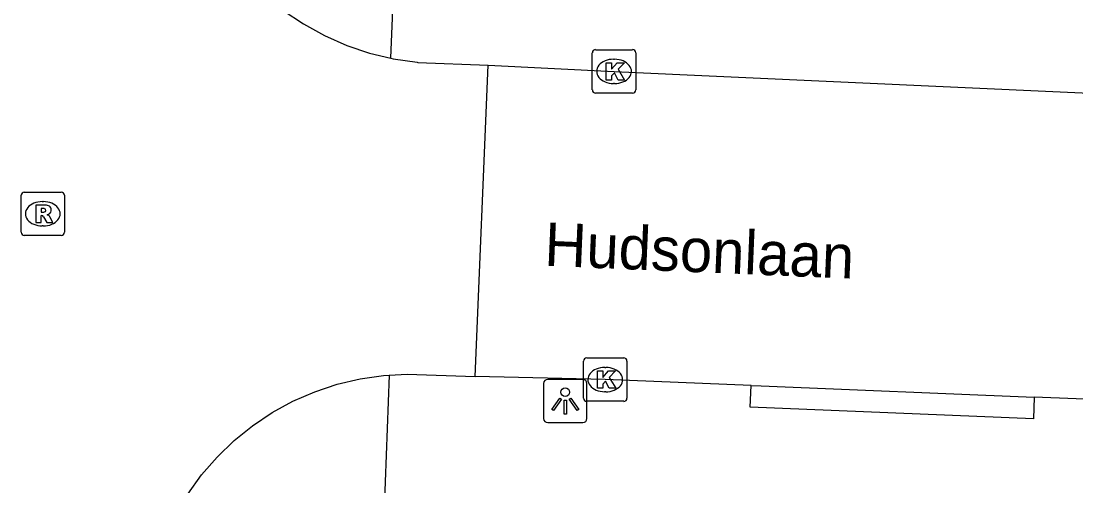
# Model space of a CAD drawing. Extents: x 161253 to 161848, y 384872 to 385383.
# Drawn here: x 161651.15 to 161675.46, y 384938.23 to 384948.95 of the extents above; entities that cross this region are included whole.
import ezdxf

# ---------------------------------------------------------------- set-up
doc = ezdxf.new("R2010")
doc.units = 0
for name, color, linetype in [('IMGEO_Kolk', 7, 'Continuous'), ('IMGEO_Lichtpunt', 7, 'Continuous'), ('IMGEO_Openbare_ruimte_label', 7, 'Continuous'), ('IMGEO_Rijbaan_lokaal_open', 7, 'Continuous'), ('IMGEO_Rioolput', 7, 'Continuous'), ('IMGEO_Voetpad_open', 7, 'Continuous')]:
    doc.layers.add(name, color=color, linetype=linetype)

msp = doc.modelspace()

# ---------------------------------------------------------------- linework, layer by layer
at = {"layer": 'IMGEO_Kolk'}
for p, q in [((161664.312, 384947.367), (161664.312, 384948.219)), ((161664.387, 384948.293), (161665.239, 384948.293)), ((161665.313, 384948.219), (161665.313, 384947.367)), ((161664.8, 384948.073), (161664.825, 384948.073)), ((161664.823, 384947.513), (161664.798, 384947.513)), ((161665.239, 384947.293), (161664.387, 384947.293)), ((161664.184, 384941.184), (161665.036, 384941.184)), ((161664.109, 384940.258), (161664.109, 384941.11)), ((161664.597, 384940.964), (161664.622, 384940.964)), ((161665.11, 384941.11), (161665.11, 384940.258)), ((161664.62, 384940.404), (161664.595, 384940.404)), ((161665.036, 384940.184), (161664.184, 384940.184))]:
    msp.add_line(p, q, dxfattribs=at)
for points in [[(161664.312, 384947.367), (161664.312, 384948.219)], [(161664.387, 384948.293), (161665.239, 384948.293)], [(161665.313, 384948.219), (161665.313, 384947.367)], [(161664.633, 384947.993), (161664.756, 384947.993), (161664.756, 384947.842), (161664.886, 384947.993), (161665.05, 384947.993), (161664.904, 384947.842), (161665.057, 384947.593), (161664.905, 384947.593), (161664.82, 384947.757), (161664.756, 384947.69), (161664.756, 384947.593), (161664.633, 384947.593), (161664.633, 384947.993)], [(161665.239, 384947.293), (161664.387, 384947.293)], [(161664.184, 384941.184), (161665.036, 384941.184)], [(161664.109, 384940.258), (161664.109, 384941.11)], [(161665.11, 384941.11), (161665.11, 384940.258)], [(161664.43, 384940.884), (161664.553, 384940.884), (161664.553, 384940.733), (161664.683, 384940.884), (161664.847, 384940.884), (161664.701, 384940.733), (161664.854, 384940.484), (161664.702, 384940.484), (161664.617, 384940.648), (161664.553, 384940.581), (161664.553, 384940.484), (161664.43, 384940.484), (161664.43, 384940.884)], [(161665.036, 384940.184), (161664.184, 384940.184)]]:
    msp.add_lwpolyline(points, dxfattribs=at)
for centre, start, end in [((161664.389, 384948.217), 91.552, 178.448), ((161664.389, 384948.217), 91.552, 178.448), ((161665.237, 384948.217), 1.552, 88.448), ((161665.237, 384948.217), 1.552, 88.448), ((161664.389, 384947.369), 181.552, 268.448), ((161664.389, 384947.369), 181.552, 268.448), ((161665.237, 384947.369), 271.552, 358.448), ((161665.237, 384947.369), 271.552, 358.448), ((161664.186, 384941.108), 91.552, 178.448), ((161664.186, 384941.108), 91.552, 178.448), ((161665.034, 384941.108), 1.552, 88.448), ((161665.034, 384941.108), 1.552, 88.448), ((161664.186, 384940.26), 181.552, 268.448), ((161664.186, 384940.26), 181.552, 268.448), ((161665.034, 384940.26), 271.552, 358.448), ((161665.034, 384940.26), 271.552, 358.448)]:
    msp.add_arc(centre, 0.0765, start, end, dxfattribs=at)
for centre, major_axis, ratio, start_param, end_param in [((161664.799, 384947.793), (-0.387, 0.002), 0.722429, 4.712389, 7.853982), ((161664.824, 384947.793), (-0.39, 0.002), 0.717154, 1.570796, 4.712389), ((161664.596, 384940.684), (-0.387, 0.002), 0.722429, 4.712389, 7.853982), ((161664.621, 384940.684), (-0.39, 0.002), 0.717154, 1.570796, 4.712389)]:
    msp.add_ellipse(centre, major_axis=major_axis, ratio=ratio, start_param=start_param, end_param=end_param, dxfattribs=at)
at = {"layer": 'IMGEO_Lichtpunt'}
for p, q in [((161664.092, 384940.691), (161663.284, 384940.691)), ((161664.092, 384940.691), (161663.284, 384940.691)), ((161663.19, 384940.596), (161663.19, 384939.789)), ((161663.19, 384940.596), (161663.19, 384939.789)), ((161664.186, 384939.789), (161664.186, 384940.596)), ((161664.186, 384939.789), (161664.186, 384940.596)), ((161663.284, 384939.695), (161664.092, 384939.695)), ((161663.284, 384939.695), (161664.092, 384939.695))]:
    msp.add_line(p, q, dxfattribs=at)
for points in [[(161663.564, 384940.26), (161663.603, 384940.232), (161663.415, 384939.97), (161663.377, 384939.997), (161663.564, 384940.26)], [(161663.666, 384940.212), (161663.713, 384940.212), (161663.713, 384939.89), (161663.666, 384939.89), (161663.666, 384940.212)], [(161663.776, 384940.232), (161663.814, 384940.259), (161664.001, 384939.997), (161663.962, 384939.969), (161663.776, 384940.232)]]:
    msp.add_lwpolyline(points, dxfattribs=at)
msp.add_circle((161663.689, 384940.394), 0.0994, dxfattribs=at)
for centre, start, end in [((161663.284, 384940.596), 90, 180), ((161663.284, 384940.596), 90, 180), ((161664.092, 384940.596), 0, 90), ((161664.092, 384940.596), 0, 90), ((161663.284, 384939.789), 180, 270), ((161663.284, 384939.789), 180, 270), ((161664.092, 384939.789), 270, 0), ((161664.092, 384939.789), 270, 360)]:
    msp.add_arc(centre, 0.0946, start, end, dxfattribs=at)
at = {"layer": 'IMGEO_Rijbaan_lokaal_open'}
for points in [[(161654.717, 384956.106), (161654.675, 384954.531), (161654.672, 384953.973), (161654.718, 384953.417), (161654.813, 384952.867), (161654.958, 384952.328), (161655.15, 384951.804), (161655.388, 384951.299), (161655.67, 384950.818), (161655.994, 384950.364), (161656.357, 384949.94), (161656.757, 384949.551), (161657.19, 384949.199), (161657.652, 384948.887), (161658.141, 384948.617), (161658.651, 384948.393), (161659.18, 384948.214), (161659.665, 384948.098)], [(161661.913, 384947.934), (161664.813, 384947.793), (161680.659, 384947.069), (161681.376, 384947.063), (161682.091, 384947.121), (161682.798, 384947.242), (161683.491, 384947.426), (161684.165, 384947.672), (161684.814, 384947.976), (161685.433, 384948.338), (161686.018, 384948.753), (161686.563, 384949.219), (161687.065, 384949.731), (161687.518, 384950.287), (161687.921, 384950.88), (161688.268, 384951.508), (161688.558, 384952.163), (161688.789, 384952.843), (161688.958, 384953.539), (161689.064, 384954.249), (161689.098, 384954.71), (161689.115, 384955.181)], [(161659.665, 384948.098), (161659.723, 384948.084), (161660.275, 384948.003), (161660.291, 384948.001), (161661.913, 384947.934)], [(161661.612, 384940.759), (161661.913, 384947.934)], [(161653.829, 384931.155), (161654.012, 384935.141), (161654.049, 384935.508), (161654.145, 384936.045), (161654.288, 384936.571), (161654.478, 384937.083), (161654.712, 384937.575), (161654.99, 384938.045), (161655.308, 384938.488), (161655.665, 384938.9), (161656.057, 384939.279), (161656.481, 384939.622), (161656.935, 384939.925), (161657.413, 384940.187), (161657.913, 384940.404), (161658.431, 384940.577), (161658.962, 384940.702), (161659.502, 384940.779), (161659.633, 384940.786)], [(161659.633, 384940.786), (161660.046, 384940.808), (161661.612, 384940.759)], [(161667.973, 384940.551), (161664.61, 384940.684), (161661.612, 384940.759)], [(161667.973, 384940.551), (161668.201, 384940.542), (161674.499, 384940.279)], [(161695.406, 384939.447), (161674.499, 384940.279)]]:
    msp.add_lwpolyline(points, dxfattribs=at)
at = {"layer": 'IMGEO_Rioolput'}
for p, q in [((161651.146, 384944.083), (161651.146, 384944.935)), ((161651.221, 384945.009), (161652.073, 384945.009)), ((161652.147, 384944.935), (161652.147, 384944.083)), ((161651.634, 384944.789), (161651.659, 384944.789)), ((161651.657, 384944.229), (161651.632, 384944.229)), ((161652.073, 384944.009), (161651.221, 384944.009))]:
    msp.add_line(p, q, dxfattribs=at)
for points in [[(161651.146, 384944.083), (161651.146, 384944.935)], [(161651.221, 384945.009), (161652.073, 384945.009)], [(161652.147, 384944.935), (161652.147, 384944.083)], [(161651.735, 384944.707), (161651.483, 384944.709), (161651.483, 384944.309)], [(161651.661, 384944.628), (161651.607, 384944.628), (161651.607, 384944.547)], [(161651.483, 384944.309), (161651.607, 384944.309), (161651.607, 384944.471), (161651.618, 384944.471)], [(161651.607, 384944.547), (161651.659, 384944.547)], [(161651.665, 384944.442), (161651.736, 384944.309), (161651.876, 384944.309), (161651.811, 384944.435)], [(161652.073, 384944.009), (161651.221, 384944.009)]]:
    msp.add_lwpolyline(points, dxfattribs=at)
for centre, radius, start, end in [((161651.223, 384944.933), 0.0765, 91.552, 178.448), ((161651.223, 384944.933), 0.0765, 91.552, 178.448), ((161652.071, 384944.933), 0.0765, 1.552, 88.448), ((161652.071, 384944.933), 0.0765, 1.552, 88.448), ((161651.667, 384944.532), 0.0964, 77.0061, 93.1865), ((161651.681, 384944.589), 0.0378, 276.6634, 79.6772), ((161651.734, 384944.597), 0.109, 350.3612, 89.416), ((161651.732, 384944.597), 0.112, 277.5842, 350.9817), ((161651.617, 384944.418), 0.0533, 26.0293, 88.6989), ((161651.643, 384944.736), 0.19, 274.7715, 282.9687), ((161651.716, 384944.382), 0.108, 29.5134, 73.7905), ((161651.223, 384944.085), 0.0765, 181.552, 268.448), ((161651.223, 384944.085), 0.0765, 181.552, 268.448), ((161652.071, 384944.085), 0.0765, 271.552, 358.448), ((161652.071, 384944.085), 0.0765, 271.552, 358.448)]:
    msp.add_arc(centre, radius, start, end, dxfattribs=at)
for centre, major_axis, ratio, start_param, end_param in [((161651.633, 384944.509), (-0.387, 0.002), 0.722429, 4.712389, 7.853982), ((161651.658, 384944.509), (-0.39, 0.002), 0.717154, 1.570796, 4.712389)]:
    msp.add_ellipse(centre, major_axis=major_axis, ratio=ratio, start_param=start_param, end_param=end_param, dxfattribs=at)
at = {"layer": 'IMGEO_Voetpad_open'}
for points in [[(161659.665, 384948.098), (161659.768, 384950.519)], [(161659.633, 384940.786), (161659.374, 384934.02)], [(161674.499, 384940.279), (161674.477, 384939.78), (161667.951, 384940.052), (161667.973, 384940.551)]]:
    msp.add_lwpolyline(points, dxfattribs=at)

# ---------------------------------------------------------------- texts
at = {"layer": 'IMGEO_Openbare_ruimte_label'}
msp.add_text('Hudsonlaan', height=1, rotation=357.5926, dxfattribs=at).set_placement((161663.195, 384943.312))

doc.saveas('drawing.dxf')
